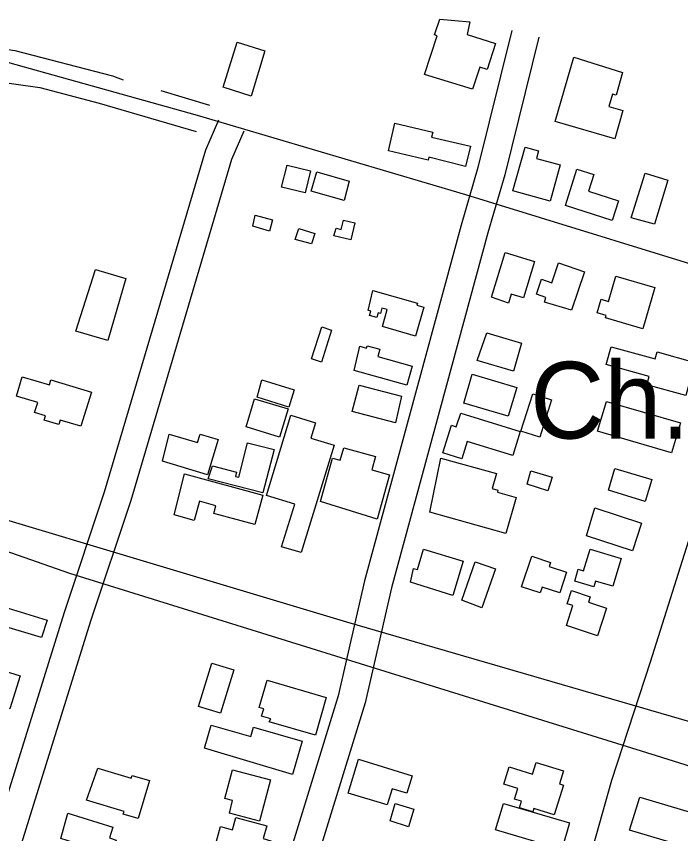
# Model space of a CAD drawing. Extents: x 3324125 to 3362000, y 600753 to 626151.
# Drawn here: x 3339347 to 3340066, y 607880 to 608764 of the extents above; entities that cross this region are included whole.
import ezdxf

# ---------------------------------------------------------------- set-up
doc = ezdxf.new("R2010")
doc.units = 0
for name, color, linetype in [('V-BLDG-OTLN', 7, 'Continuous'), ('V-ROAD-CNTR', 7, 'Continuous'), ('V-SITE-OTLN-IDEN', 7, 'Continuous'), ('V-TOPO-SHOR', 7, 'Continuous')]:
    doc.layers.add(name, color=color, linetype=linetype)

msp = doc.modelspace()

# ---------------------------------------------------------------- linework, layer by layer
at = {"layer": 'V-BLDG-OTLN'}
for points in [[(3339788.83, 608701.29), (3339802.3, 608743.06), (3339799.72, 608743.89), (3339805.25, 608761.03), (3339837.7, 608758.08), (3339835.02, 608744.58), (3339865.52, 608734.74), (3339856.45, 608706.64), (3339848.57, 608709.19), (3339840.82, 608685.18)], [(3339571.15, 608687.59), (3339586, 608735.96), (3339616.21, 608726.69), (3339601.21, 608677.82)], [(3339950.12, 608719.73), (3340002.92, 608703.16), (3339995.88, 608678.69), (3339991.89, 608679.83), (3339988.08, 608666.59), (3340003.37, 608662.19), (3339994.57, 608631.59), (3339930.1, 608650.13)], [(3339833.22, 608601.57), (3339793.38, 608611.74), (3339792.61, 608608.5), (3339749.67, 608618.62), (3339756.69, 608648.4), (3339797.69, 608638.73), (3339796.43, 608633.39), (3339838.39, 608623.49)], [(3339884.36, 608575.25), (3339897.64, 608622.44), (3339912.05, 608618.5), (3339909.82, 608610.35), (3339935.43, 608603.34), (3339924.73, 608564.21)], [(3339634.24, 608579.35), (3339640.23, 608602.88), (3339665.4, 608596.73), (3339659.64, 608573.14)], [(3339941.09, 608559.38), (3339953.35, 608598.68), (3339971.72, 608592.89), (3339966.02, 608574.81), (3339998.39, 608564.4), (3339991.55, 608543.14)], [(3339701.75, 608564.89), (3339666.25, 608574.9), (3339672.12, 608595.72), (3339707.26, 608585.82)], [(3340012.42, 608545.97), (3340027.26, 608594.35), (3340051.92, 608586.78), (3340037.31, 608539.19)], [(3339602.96, 608536.92), (3339605.74, 608549.08), (3339624.49, 608543.72), (3339621.06, 608531.74)], [(3339690.63, 608526.68), (3339693.13, 608534.74), (3339698.74, 608533.37), (3339701.24, 608543.67), (3339713.56, 608540.67), (3339709.07, 608522.2)], [(3339648.9, 608522.76), (3339652.7, 608534.59), (3339670.13, 608529), (3339666.63, 608518.09)], [(3339861.32, 608460.08), (3339875.82, 608508.45), (3339907.72, 608498.89), (3339895.91, 608459.47), (3339882.45, 608463.51), (3339879.55, 608453.84)], [(3339947.6, 608446.01), (3339918.4, 608454.87), (3339920.12, 608459.94), (3339909.78, 608463.45), (3339915.24, 608479.56), (3339926.39, 608475.78), (3339933.69, 608497.3), (3339961.77, 608487.78)], [(3339432.82, 608490.08), (3339465.88, 608480.42), (3339446.23, 608413.19), (3339411.77, 608423.26)], [(3339995.51, 608482.98), (3340037.97, 608470.56), (3340024.97, 608426.13), (3339984.54, 608437.96), (3339985.23, 608440.32), (3339975.4, 608443.2), (3339979.72, 608457.95), (3339987.62, 608455.64)], [(3339732.79, 608467.45), (3339781.16, 608453.64), (3339780.54, 608451.45), (3339788.05, 608449.31), (3339779.16, 608418.14), (3339743.23, 608428.39), (3339748.48, 608446.75), (3339742.71, 608448.4), (3339741, 608442.42), (3339738.62, 608443.1), (3339737.19, 608438.08), (3339729.39, 608440.31), (3339730.72, 608444.94), (3339727.83, 608445.76)], [(3339666.52, 608393.57), (3339677.58, 608428.02), (3339688.28, 608424.59), (3339677.18, 608389.97)], [(3339856.19, 608421.46), (3339893.77, 608410.42), (3339884.92, 608380.31), (3339845.69, 608391.84)], [(3339712.59, 608380.93), (3339718.67, 608407.25), (3339726.14, 608405.18), (3339726.8, 608407.57), (3339740.39, 608403.79), (3339738.21, 608395.95), (3339775.38, 608385.62), (3339769.66, 608365.05)], [(3339985.29, 608387.32), (3339990.75, 608406.6), (3340038.22, 608393.51), (3340040.27, 608400.96), (3340081.12, 608389.69), (3340071.19, 608353.69), (3340029.03, 608365.31), (3340031.58, 608374.55)], [(3339831.31, 608345.59), (3339840.46, 608376.81), (3339888.54, 608362.65), (3339879.34, 608331.44)], [(3339384.62, 608370.77), (3339428.44, 608357.48), (3339417.21, 608320.48), (3339394.79, 608327.28), (3339393.3, 608322.35), (3339377.33, 608327.19), (3339378.76, 608331.92), (3339367.07, 608335.46), (3339370.4, 608346.41), (3339347.5, 608353.2), (3339353.72, 608374.15), (3339383.01, 608365.46)], [(3339612.67, 608370.84), (3339647.82, 608359.79), (3339641.99, 608341.23), (3339607.95, 608351.93)], [(3339757.23, 608324.33), (3339710.6, 608336.4), (3339717.97, 608364.88), (3339763.9, 608352.99)], [(3339632.1, 608308.87), (3339595.9, 608319.78), (3339605.06, 608350.17), (3339641.26, 608339.25)], [(3339926.18, 608348.97), (3339913.41, 608308.89), (3339892.94, 608315.39), (3339905.72, 608355.49)], [(3339985.73, 608347.32), (3340065.43, 608324.2), (3340056.04, 608291.84), (3339975.73, 608315.14)], [(3339655.51, 608183.82), (3339634.26, 608189.98), (3339648.38, 608236.14), (3339617.75, 608245.51), (3339644.34, 608332.44), (3339670.74, 608324.36), (3339665.68, 608307.83), (3339691.08, 608300.06)], [(3339827.86, 608334.8), (3339892.25, 608314.77), (3339884.15, 608288.73), (3339834.94, 608304.04), (3339829.11, 608285.31), (3339808.52, 608291.72), (3339817.81, 608321.57), (3339822.95, 608319.97)], [(3339505.4, 608282.61), (3339512.57, 608311.96), (3339543.29, 608302.82), (3339546.05, 608312.11), (3339565.49, 608306.33), (3339554.12, 608268.11)], [(3339554.82, 608263.59), (3339559.52, 608277.57), (3339585.5, 608270.9), (3339584.34, 608266.36), (3339587.84, 608265.46), (3339597.36, 608302.59), (3339625.99, 608295.24), (3339613.98, 608248.42)], [(3339676.26, 608239.17), (3339689.37, 608286.15), (3339697.59, 608283.85), (3339701.32, 608297.22), (3339735.63, 608287.65), (3339731.64, 608273.35), (3339750.76, 608268.02), (3339737.39, 608220.11)], [(3339794.36, 608227.61), (3339806.52, 608286.12), (3339866.48, 608269.32), (3339861.94, 608253.14), (3339868.19, 608251.39), (3339867.56, 608249.14), (3339887.77, 608243.48), (3339876.84, 608204.49)], [(3339899.85, 608257.75), (3339903.75, 608272.48), (3339926.63, 608265.39), (3339922.12, 608250.84)], [(3339987.68, 608251.34), (3339994.52, 608275), (3340034.53, 608262.82), (3340027.36, 608239.25)], [(3339518.04, 608224.55), (3339529.3, 608269.11), (3339613.79, 608246.15), (3339605.11, 608214.21), (3339560.73, 608226.27), (3339562.99, 608234.61), (3339545.26, 608239.43), (3339539.62, 608218.69)], [(3339973.12, 608232.18), (3340023.58, 608215.59), (3340013.74, 608185.64), (3339964, 608201.98)], [(3339773.66, 608151.74), (3339776.82, 608166.75), (3339781.16, 608165.5), (3339787.57, 608187.65), (3339830.72, 608174.52), (3339819.25, 608137.58)], [(3339968, 608187.65), (3340001.41, 608177.63), (3339992.38, 608147.51), (3339973.78, 608153.08), (3339971.86, 608146.66), (3339951.2, 608152.85), (3339955.07, 608165.79), (3339960.86, 608164.05)], [(3339829, 608132.39), (3339843.52, 608173.81), (3339865.39, 608166.14), (3339850.6, 608123.96)], [(3339893.66, 608146.79), (3339904.72, 608179.85), (3339924.98, 608173.08), (3339923.58, 608168.89), (3339942.48, 608162.57), (3339934.98, 608140.17), (3339916.06, 608146.5), (3339914, 608140.34)], [(3339942.45, 608104.82), (3339949.04, 608126.5), (3339942.88, 608128.54), (3339947.58, 608142.74), (3339968.04, 608135.97), (3339966.11, 608130.12), (3339985.74, 608123.62), (3339975.86, 608093.76)], [(3339374.41, 608091.85), (3339328.44, 608105.83), (3339329.16, 608108.21), (3339318.89, 608111.34), (3339323.95, 608127.95), (3339380.65, 608110.7)], [(3339287.56, 608070.2), (3339351.31, 608050.62), (3339340.35, 608014.92), (3339334.83, 608016.62), (3339331.06, 608004.34), (3339300.52, 608013.72), (3339304.37, 608026.24), (3339276.77, 608034.71)], [(3339544.29, 608017.39), (3339558.75, 608064.39), (3339582.42, 608057.11), (3339567.96, 608010.14)], [(3339620.79, 608000.81), (3339622.55, 608003.98), (3339612.63, 608006.86), (3339614.92, 608014.76), (3339610.08, 608016.16), (3339618.65, 608045.75), (3339682.56, 608027.25), (3339670.71, 607986.35)], [(3339646.05, 607943.69), (3339550.88, 607972.15), (3339558.19, 607997.29), (3339600.81, 607984.91), (3339603.77, 607995.09), (3339656.53, 607979.77)], [(3339748.45, 607910.78), (3339706.09, 607923.44), (3339717.51, 607960.27), (3339775.4, 607942.32), (3339769.54, 607923.41), (3339753.87, 607928.27)], [(3339906.95, 607906.88), (3339905.81, 607903.21), (3339891.3, 607907.73), (3339893.54, 607914.91), (3339886.08, 607917.23), (3339889.58, 607928.47), (3339874.43, 607933.18), (3339880.33, 607952.13), (3339905.62, 607944.26), (3339909.55, 607956.89), (3339938.93, 607947.74), (3339934.58, 607933.77), (3339939.14, 607932.34), (3339929.07, 607899.99)], [(3339435.56, 607950.51), (3339471.63, 607939.66), (3339472.57, 607942.79), (3339491.39, 607937.13), (3339479.05, 607896.07), (3339462.96, 607900.9), (3339463.81, 607903.72), (3339423.07, 607915.97)], [(3339577.68, 607902.03), (3339581.22, 607915.53), (3339572.97, 607917.71), (3339581.16, 607948.68), (3339622.23, 607937.83), (3339610.47, 607893.36)], [(3340021.54, 607919.4), (3340095.52, 607897.35), (3340092.12, 607885.96), (3340096.84, 607884.55), (3340089.55, 607860.08), (3340010.27, 607883.71)], [(3339751.76, 607893.68), (3339757.18, 607912.26), (3339777.27, 607906.4), (3339771.61, 607887.02)], [(3339874, 607912.44), (3339945.56, 607891.36), (3339937.12, 607862.7), (3339865.56, 607883.78)], [(3339395.3, 607874.67), (3339403.16, 607901.89), (3339451.56, 607886.62), (3339447.91, 607875.07), (3339455.2, 607872.77), (3339450.33, 607857.32)], [(3339546.46, 607859.71), (3339549.9, 607871.23), (3339562.63, 607867.77), (3339567.99, 607887.49), (3339580.95, 607883.97), (3339584.56, 607897.26), (3339618.1, 607888.14), (3339614.36, 607874.37), (3339622.61, 607872.13), (3339614.23, 607841.29)]]:
    msp.add_lwpolyline(points, close=True, dxfattribs=at)
at = {"layer": 'V-ROAD-CNTR'}
for points in [[(3338176.34, 609071.9), (3338350.5, 609000.51), (3338614.34, 608891.18), (3338770.27, 608820.42), (3338891.36, 608776.44), (3338927.81, 608763.62), (3338950.61, 608754.45), (3338978.41, 608743.71), (3339005.1, 608739.39), (3339056.12, 608731.64), (3339096.58, 608726.71), (3339168.31, 608727.57), (3339265.35, 608720.71), (3339321.95, 608718.77), (3339543.05, 608656.99), (3339833.05, 608571.35), (3340151.54, 608473.12)], [(3339883.13, 608748.56), (3339846.52, 608600.35), (3339828.23, 608538.17), (3339723.75, 608153.14), (3339695.48, 608029.05), (3339590.41, 607687.64), (3339546.26, 607497.35)], [(3339912.26, 608741.37), (3339875.49, 608592.52), (3339857.1, 608530), (3339752.87, 608145.87), (3339724.49, 608021.29), (3339619.4, 607679.83), (3339574.42, 607485.96)], [(3339242.25, 607613.28), (3339248.88, 607636.25), (3339399.41, 608119.22), (3339442.79, 608249.57), (3339552.28, 608619.77), (3339566.3, 608652.04)], [(3339271.07, 607604.96), (3339277.62, 607627.62), (3339427.97, 608110.02), (3339471.41, 608240.57), (3339580.53, 608609.5), (3339593.82, 608640.09)], [(3339432.08, 606157.13), (3339565.59, 606591.71), (3339595.22, 606701.54), (3339779.91, 607255.77), (3339850.82, 607457.2), (3339938.73, 607750.37), (3339991.43, 607937.56), (3340033.26, 608065.6), (3340109.3, 608306.49), (3340151.54, 608473.12)], [(3338095.14, 608382.36), (3338259.06, 608370.58), (3338551.7, 608360.93), (3338678.85, 608355.45), (3338759.93, 608349.79), (3338867.88, 608336.94), (3338938.4, 608324.44), (3339016.79, 608313.13), (3339100.95, 608289.9), (3339704.35, 608109.04), (3340246.41, 607951.2), (3340394.49, 607900.48), (3340541.49, 607848.38), (3340714.93, 607769.87), (3340880.14, 607681.75)], [(3338030.8, 608297.17), (3338260.61, 608280.26), (3338440.83, 608273.79), (3338606.68, 608268.33), (3338780.21, 608265.07), (3338943.38, 608261.04), (3339024.43, 608253.51), (3339134.05, 608234.55), (3339262.56, 608211.24), (3339404.79, 608161.61), (3340039.21, 607964.42), (3340279.06, 607888.89), (3340451.7, 607835.6), (3340556.03, 607801.31), (3340664.65, 607748.63), (3340802.72, 607681.71)]]:
    msp.add_lwpolyline(points, dxfattribs=at)
at = {"layer": 'V-TOPO-SHOR'}
msp.add_line((3339503.48, 608683.91), (3339556.07, 608667.82), dxfattribs=at)
for points in [[(3338647.06, 608899.75), (3338753.77, 608856.44), (3338884.84, 608801.47), (3338947.06, 608775.78), (3339032.71, 608753.45), (3339096.4, 608743.98), (3339147.17, 608739.28), (3339256.49, 608735.62), (3339318.67, 608730.96), (3339345.71, 608727.11), (3339451.18, 608699.72), (3339462.91, 608695.54)], [(3339313.65, 608695.51), (3339372.83, 608686.93), (3339436.84, 608669.95), (3339541.72, 608639.55)]]:
    msp.add_lwpolyline(points, dxfattribs=at)

# ---------------------------------------------------------------- texts
at = {"layer": 'V-SITE-OTLN-IDEN'}
msp.add_text('Ch.', height=83, dxfattribs=at).set_placement((3339903, 608307.26))

doc.saveas('drawing.dxf')
